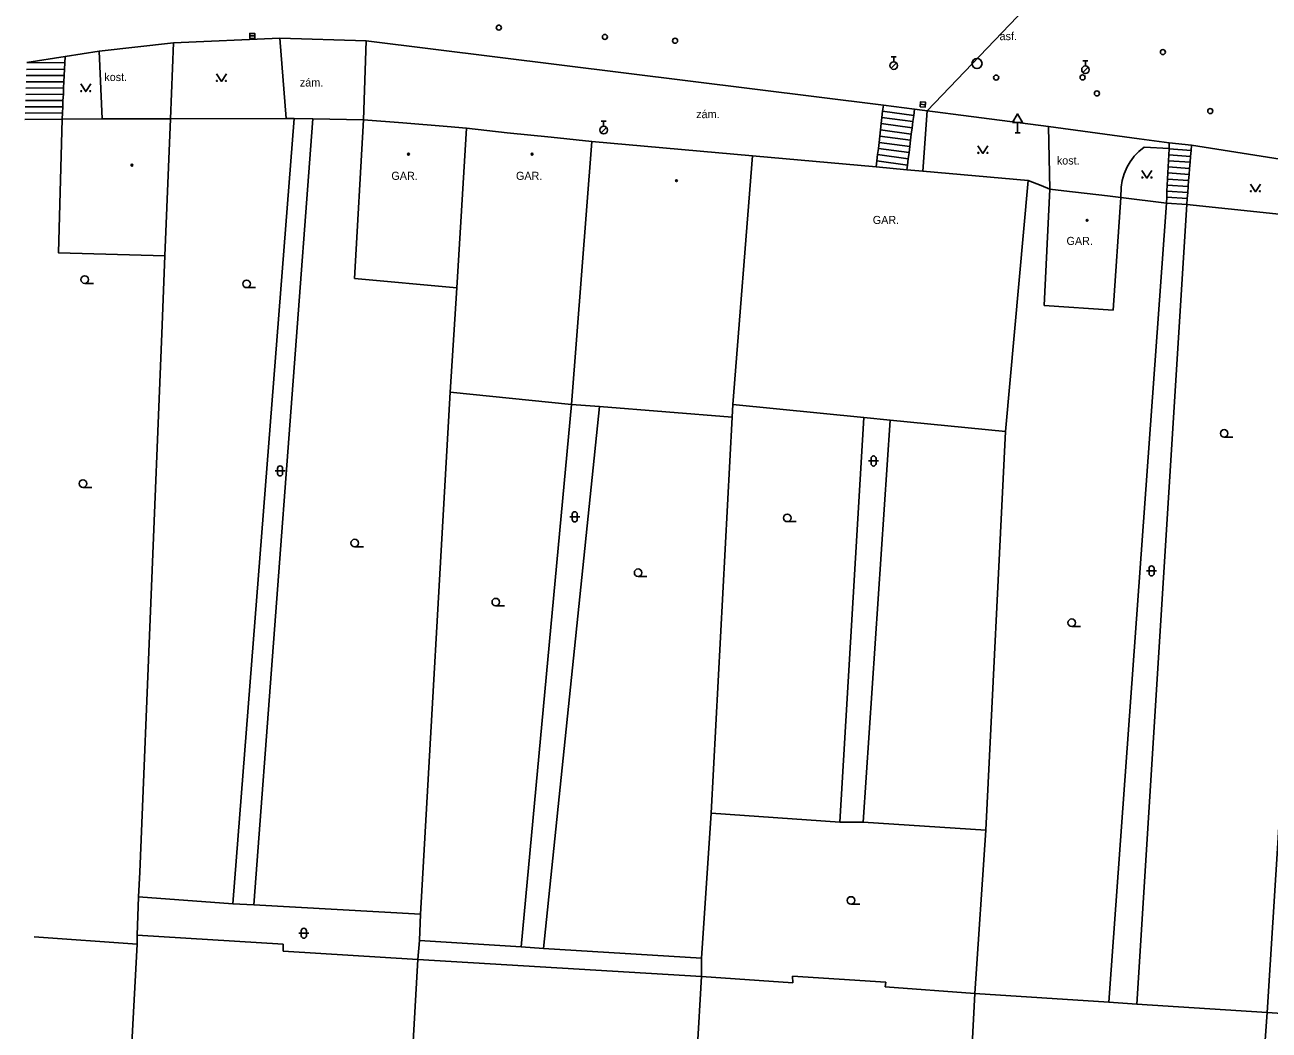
# Model space of a CAD drawing. Extents: x -599770 to -598493, y -1162076 to -1159209.
# Drawn here: x -599538.4 to -599476.7, y -1161787.4 to -1161737.6 of the extents above; entities that cross this region are included whole.
import ezdxf

# ---------------------------------------------------------------- set-up
doc = ezdxf.new("R2010")
doc.units = 0
doc.layers.add('Podklad', color=7, linetype='Continuous')

msp = doc.modelspace()

# ---------------------------------------------------------------- linework, layer by layer
at = {"layer": 'Podklad'}
for p, q in [((-599527.265, -1161738.12), (-599527.015, -1161738.12)), ((-599495.449, -1161739.726), (-599495.184, -1161739.461)), ((-599495.445, -1161739.152), (-599495.195, -1161739.152)), ((-599495.32, -1161739.402), (-599495.32, -1161739.152)), ((-599485.935, -1161739.363), (-599485.685, -1161739.363)), ((-599485.81, -1161739.613), (-599485.81, -1161739.363)), ((-599485.939, -1161739.936), (-599485.674, -1161739.671)), ((-599494.004, -1161741.508), (-599493.756, -1161741.532)), ((-599509.835, -1161742.352), (-599509.585, -1161742.352)), ((-599509.71, -1161742.602), (-599509.71, -1161742.352)), ((-599489.18, -1161742.421), (-599489.18, -1161742.93)), ((-599509.839, -1161742.926), (-599509.574, -1161742.661)), ((-599489.305, -1161742.93), (-599489.055, -1161742.93)), ((-599535.45, -1161750.398), (-599535.012, -1161750.398)), ((-599527.42, -1161750.608), (-599526.983, -1161750.608)), ((-599478.93, -1161758.027), (-599478.492, -1161758.027)), ((-599496.573, -1161759.208), (-599496.073, -1161759.208)), ((-599496.448, -1161759.083), (-599496.448, -1161759.333)), ((-599496.198, -1161759.083), (-599496.198, -1161759.333)), ((-599526.013, -1161759.698), (-599525.513, -1161759.698)), ((-599525.888, -1161759.573), (-599525.888, -1161759.823)), ((-599525.638, -1161759.573), (-599525.638, -1161759.823)), ((-599535.54, -1161760.517), (-599535.102, -1161760.517)), ((-599511.393, -1161761.978), (-599510.893, -1161761.978)), ((-599511.268, -1161761.853), (-599511.268, -1161762.103)), ((-599511.018, -1161761.853), (-599511.018, -1161762.103)), ((-599500.6, -1161762.218), (-599500.163, -1161762.218)), ((-599522.06, -1161763.468), (-599521.622, -1161763.468)), ((-599482.783, -1161764.658), (-599482.283, -1161764.658)), ((-599482.658, -1161764.533), (-599482.658, -1161764.783)), ((-599482.408, -1161764.533), (-599482.408, -1161764.783)), ((-599508, -1161764.938), (-599507.562, -1161764.938)), ((-599515.06, -1161766.398), (-599514.622, -1161766.398)), ((-599486.49, -1161767.418), (-599486.052, -1161767.418)), ((-599497.44, -1161781.198), (-599497.003, -1161781.198)), ((-599524.833, -1161782.638), (-599524.333, -1161782.638)), ((-599524.708, -1161782.513), (-599524.708, -1161782.763)), ((-599524.458, -1161782.513), (-599524.458, -1161782.763))]:
    msp.add_line(p, q, dxfattribs=at)
for points in [[(-599493.87, -1161744.83), (-599493.663, -1161741.84), (-599482.137, -1161729.776)], [(-599525.77, -1161738.23), (-599531.05, -1161738.47)], [(-599521.49, -1161738.36), (-599525.77, -1161738.23)], [(-599525.77, -1161738.23), (-599525.46, -1161742.21)], [(-599536.42, -1161739.14), (-599534.74, -1161738.87)], [(-599531.05, -1161738.47), (-599534.74, -1161738.87)], [(-599534.74, -1161738.87), (-599534.59, -1161742.23)], [(-599531.05, -1161738.47), (-599531.2, -1161742.23)], [(-599521.49, -1161738.36), (-599521.62, -1161742.28)], [(-599495.83, -1161741.55), (-599521.49, -1161738.36)], [(-599538.32, -1161739.44), (-599536.42, -1161739.14)], [(-599536.44, -1161739.46), (-599538.32, -1161739.44)], [(-599536.44, -1161739.46), (-599536.45, -1161739.77)], [(-599536.42, -1161739.14), (-599536.44, -1161739.46)], [(-599536.47, -1161740.08), (-599538.35, -1161740.09)], [(-599536.45, -1161739.77), (-599538.34, -1161739.78)], [(-599536.47, -1161740.08), (-599536.48, -1161740.39)], [(-599536.45, -1161739.77), (-599536.47, -1161740.08)], [(-599528.92, -1161740.005), (-599528.67, -1161740.38), (-599528.42, -1161740.005)], [(-599536.5, -1161740.7), (-599538.37, -1161740.71)], [(-599536.48, -1161740.39), (-599538.36, -1161740.4)], [(-599536.5, -1161740.7), (-599536.51, -1161741.01)], [(-599536.48, -1161740.39), (-599536.5, -1161740.7)], [(-599535.65, -1161740.505), (-599535.4, -1161740.88), (-599535.15, -1161740.505)], [(-599536.53, -1161741.32), (-599538.39, -1161741.33)], [(-599536.51, -1161741.01), (-599538.38, -1161741.02)], [(-599536.53, -1161741.32), (-599536.54, -1161741.63)], [(-599536.51, -1161741.01), (-599536.53, -1161741.32)], [(-599536.55, -1161741.94), (-599538.41, -1161741.95)], [(-599536.54, -1161741.63), (-599538.4, -1161741.64)], [(-599536.55, -1161741.94), (-599536.57, -1161742.25)], [(-599536.54, -1161741.63), (-599536.55, -1161741.94)], [(-599495.87, -1161741.86), (-599495.91, -1161742.17)], [(-599495.83, -1161741.55), (-599495.87, -1161741.86)], [(-599494.33, -1161742.07), (-599495.87, -1161741.86)], [(-599494.29, -1161741.76), (-599495.83, -1161741.55)], [(-599494.29, -1161741.76), (-599494.33, -1161742.07)], [(-599487.64, -1161742.61), (-599494.29, -1161741.76)], [(-599536.57, -1161742.25), (-599538.42, -1161742.26)], [(-599536.57, -1161742.25), (-599536.76, -1161748.88), (-599531.48, -1161749.03)], [(-599536.57, -1161742.25), (-599534.59, -1161742.23), (-599531.2, -1161742.23)], [(-599531.2, -1161742.23), (-599531.48, -1161749.03)], [(-599531.2, -1161742.23), (-599525.46, -1161742.21)], [(-599528.1, -1161781.17), (-599525.06, -1161742.22)], [(-599524.13, -1161742.24), (-599527.07, -1161781.22)], [(-599525.06, -1161742.22), (-599525.46, -1161742.21)], [(-599521.62, -1161742.28), (-599524.13, -1161742.24), (-599525.06, -1161742.22)], [(-599521.62, -1161742.28), (-599522.07, -1161750.16)], [(-599519.67, -1161742.44), (-599521.62, -1161742.28)], [(-599517.48, -1161742.62), (-599519.67, -1161742.44)], [(-599495.94, -1161742.47), (-599495.98, -1161742.78)], [(-599495.91, -1161742.17), (-599495.94, -1161742.47)], [(-599494.41, -1161742.68), (-599495.94, -1161742.47)], [(-599494.37, -1161742.37), (-599495.91, -1161742.17)], [(-599494.37, -1161742.37), (-599494.41, -1161742.68)], [(-599494.33, -1161742.07), (-599494.37, -1161742.37)], [(-599516.52, -1161742.7), (-599517.48, -1161742.62)], [(-599517, -1161750.61), (-599516.52, -1161742.7)], [(-599516.52, -1161742.7), (-599514.5, -1161742.92)], [(-599514.5, -1161742.92), (-599512.31, -1161743.15)], [(-599512.31, -1161743.15), (-599510.3, -1161743.36)], [(-599496.01, -1161743.09), (-599496.05, -1161743.4)], [(-599495.98, -1161742.78), (-599496.01, -1161743.09)], [(-599494.49, -1161743.3), (-599496.01, -1161743.09)], [(-599494.45, -1161742.99), (-599495.98, -1161742.78)], [(-599494.45, -1161742.99), (-599494.49, -1161743.3)], [(-599494.41, -1161742.68), (-599494.45, -1161742.99)], [(-599483.14, -1161743.22), (-599487.64, -1161742.61)], [(-599487.64, -1161742.61), (-599487.57, -1161745.72)], [(-599511.31, -1161756.4), (-599510.3, -1161743.36)], [(-599510.3, -1161743.36), (-599502.33, -1161744.07)], [(-599496.08, -1161743.7), (-599496.12, -1161744.01)], [(-599496.05, -1161743.4), (-599496.08, -1161743.7)], [(-599494.56, -1161743.91), (-599496.08, -1161743.7)], [(-599494.52, -1161743.6), (-599496.05, -1161743.4)], [(-599494.52, -1161743.6), (-599494.56, -1161743.91)], [(-599494.49, -1161743.3), (-599494.52, -1161743.6)], [(-599491.15, -1161743.575), (-599490.9, -1161743.95), (-599490.65, -1161743.575)], [(-599484.06, -1161746.13), (-599484.036, -1161745.631), (-599483.988, -1161745.296), (-599483.898, -1161744.969), (-599483.743, -1161744.614), (-599483.598, -1161744.362), (-599483.432, -1161744.143), (-599483.393, -1161744.092), (-599483.156, -1161743.85), (-599482.89, -1161743.64), (-599481.66, -1161743.7)], [(-599481.65, -1161743.43), (-599483.14, -1161743.22)], [(-599481.66, -1161743.72), (-599481.68, -1161744.02)], [(-599481.65, -1161743.43), (-599481.66, -1161743.7), (-599481.66, -1161743.72)], [(-599480.57, -1161743.8), (-599481.66, -1161743.72)], [(-599480.55, -1161743.54), (-599481.65, -1161743.43)], [(-599480.57, -1161743.8), (-599480.6, -1161744.1)], [(-599480.55, -1161743.54), (-599480.57, -1161743.8)], [(-599474.58, -1161744.48), (-599480.55, -1161743.54)], [(-599502.33, -1161744.07), (-599496.19, -1161744.62), (-599494.67, -1161744.76), (-599493.87, -1161744.83), (-599488.65, -1161745.29), (-599489.78, -1161757.75), (-599495.5, -1161757.18), (-599496.81, -1161757.05), (-599503.3, -1161756.41)], [(-599503.3, -1161756.41), (-599502.33, -1161744.07)], [(-599496.16, -1161744.32), (-599496.19, -1161744.62)], [(-599496.12, -1161744.01), (-599496.16, -1161744.32)], [(-599494.64, -1161744.53), (-599496.16, -1161744.32)], [(-599494.6, -1161744.22), (-599496.12, -1161744.01)], [(-599494.6, -1161744.22), (-599494.64, -1161744.53)], [(-599494.56, -1161743.91), (-599494.6, -1161744.22)], [(-599481.69, -1161744.32), (-599481.71, -1161744.62)], [(-599481.68, -1161744.02), (-599481.69, -1161744.32)], [(-599480.62, -1161744.39), (-599481.69, -1161744.32)], [(-599480.6, -1161744.1), (-599481.68, -1161744.02)], [(-599480.62, -1161744.39), (-599480.65, -1161744.69)], [(-599480.6, -1161744.1), (-599480.62, -1161744.39)], [(-599494.64, -1161744.53), (-599494.67, -1161744.76)], [(-599483.01, -1161744.795), (-599482.76, -1161745.17), (-599482.51, -1161744.795)], [(-599481.72, -1161744.92), (-599481.74, -1161745.22)], [(-599481.71, -1161744.62), (-599481.72, -1161744.92)], [(-599480.67, -1161744.99), (-599481.72, -1161744.92)], [(-599480.65, -1161744.69), (-599481.71, -1161744.62)], [(-599480.67, -1161744.99), (-599480.7, -1161745.29)], [(-599480.65, -1161744.69), (-599480.67, -1161744.99)], [(-599488.65, -1161745.29), (-599488, -1161745.54), (-599487.57, -1161745.72)], [(-599481.75, -1161745.52), (-599481.77, -1161745.82)], [(-599481.74, -1161745.22), (-599481.75, -1161745.52)], [(-599480.72, -1161745.59), (-599481.75, -1161745.52)], [(-599480.7, -1161745.29), (-599481.74, -1161745.22)], [(-599480.72, -1161745.59), (-599480.74, -1161745.89)], [(-599480.7, -1161745.29), (-599480.72, -1161745.59)], [(-599477.63, -1161745.475), (-599477.38, -1161745.85), (-599477.13, -1161745.475)], [(-599487.86, -1161751.49), (-599487.57, -1161745.72)], [(-599487.57, -1161745.72), (-599486.89, -1161745.8)], [(-599486.89, -1161745.8), (-599484.71, -1161746.05)], [(-599484.71, -1161746.05), (-599484.06, -1161746.13)], [(-599484.06, -1161746.13), (-599484.44, -1161751.72)], [(-599484.06, -1161746.13), (-599481.79, -1161746.42)], [(-599481.78, -1161746.12), (-599481.79, -1161746.42)], [(-599481.77, -1161745.82), (-599481.78, -1161746.12)], [(-599480.76, -1161746.19), (-599481.78, -1161746.12)], [(-599480.74, -1161745.89), (-599481.77, -1161745.82)], [(-599480.76, -1161746.19), (-599480.78, -1161746.49)], [(-599480.74, -1161745.89), (-599480.76, -1161746.19)], [(-599481.79, -1161746.42), (-599484.65, -1161786.06)], [(-599483.27, -1161786.15), (-599480.78, -1161746.49)], [(-599480.78, -1161746.49), (-599481.79, -1161746.42)], [(-599480.78, -1161746.49), (-599474.32, -1161747.16), (-599474.5, -1161750.06), (-599476.8, -1161786.57)], [(-599531.48, -1161749.03), (-599531.63, -1161752.89)], [(-599522.07, -1161750.16), (-599517, -1161750.61)], [(-599517.32, -1161755.8), (-599517, -1161750.61)], [(-599484.44, -1161751.72), (-599487.86, -1161751.49)], [(-599531.63, -1161752.89), (-599532.71, -1161779.61)], [(-599517.32, -1161755.8), (-599518.8, -1161781.69)], [(-599517.32, -1161755.8), (-599511.31, -1161756.4)], [(-599511.31, -1161756.4), (-599513.81, -1161783.31)], [(-599512.69, -1161783.4), (-599509.91, -1161756.51)], [(-599511.31, -1161756.4), (-599509.91, -1161756.51), (-599503.33, -1161757.03)], [(-599503.3, -1161756.41), (-599503.33, -1161757.03), (-599504.38, -1161776.68)], [(-599497.99, -1161777.12), (-599496.81, -1161757.05)], [(-599495.5, -1161757.18), (-599496.84, -1161777.12)], [(-599489.78, -1161757.75), (-599490.76, -1161777.53)], [(-599504.38, -1161776.68), (-599504.85, -1161783.88)], [(-599504.38, -1161776.68), (-599497.99, -1161777.12)], [(-599497.99, -1161777.12), (-599496.84, -1161777.12)], [(-599496.84, -1161777.12), (-599490.76, -1161777.53)], [(-599490.76, -1161777.53), (-599491.29, -1161785.62)], [(-599532.71, -1161779.61), (-599532.78, -1161780.83)], [(-599532.78, -1161780.83), (-599532.85, -1161782.74)], [(-599532.78, -1161780.83), (-599528.1, -1161781.17)], [(-599528.1, -1161781.17), (-599527.07, -1161781.22)], [(-599527.07, -1161781.22), (-599518.8, -1161781.69)], [(-599518.8, -1161781.69), (-599518.85, -1161783)], [(-599537.96, -1161782.82), (-599532.85, -1161783.18)], [(-599532.85, -1161783.18), (-599533.41, -1161793.62)], [(-599532.85, -1161782.74), (-599525.6, -1161783.18)], [(-599532.85, -1161783.18), (-599532.85, -1161782.74)], [(-599525.6, -1161783.18), (-599525.61, -1161783.53)], [(-599518.85, -1161783), (-599518.92, -1161783.94)], [(-599513.81, -1161783.31), (-599518.85, -1161783)], [(-599512.69, -1161783.4), (-599513.81, -1161783.31)], [(-599525.61, -1161783.53), (-599518.92, -1161783.94)], [(-599519.53, -1161794.4), (-599518.92, -1161783.94)], [(-599518.92, -1161783.94), (-599504.86, -1161784.78)], [(-599504.85, -1161783.88), (-599512.69, -1161783.4)], [(-599504.85, -1161783.88), (-599504.86, -1161784.78)], [(-599505.5, -1161795.9), (-599504.86, -1161784.78)], [(-599504.86, -1161784.78), (-599500.33, -1161785.09)], [(-599500.33, -1161785.09), (-599500.35, -1161784.77)], [(-599500.35, -1161784.77), (-599495.71, -1161785.06)], [(-599495.71, -1161785.06), (-599495.75, -1161785.3)], [(-599495.75, -1161785.3), (-599491.29, -1161785.62)], [(-599491.29, -1161785.62), (-599491.92, -1161797.71)], [(-599491.29, -1161785.62), (-599484.65, -1161786.06)], [(-599484.65, -1161786.06), (-599483.27, -1161786.15)], [(-599483.27, -1161786.15), (-599476.8, -1161786.57)], [(-599477.58, -1161797.39), (-599476.8, -1161786.57)], [(-599476.8, -1161786.57), (-599472.78, -1161786.84)]]:
    msp.add_lwpolyline(points, dxfattribs=at)
for points in [[(-599527.265, -1161738.245), (-599527.015, -1161738.245), (-599527.015, -1161737.995), (-599527.265, -1161737.995)], [(-599494.016, -1161741.633), (-599493.767, -1161741.656), (-599493.744, -1161741.407), (-599493.993, -1161741.384)], [(-599489.43, -1161742.421), (-599488.93, -1161742.421), (-599489.18, -1161741.988)]]:
    msp.add_lwpolyline(points, close=True, dxfattribs=at)
for centre, radius in [((-599514.91, -1161737.71), 0.125), ((-599509.65, -1161738.17), 0.125), ((-599506.17, -1161738.36), 0.125), ((-599481.97, -1161738.92), 0.125), ((-599495.32, -1161739.59), 0.188), ((-599491.19, -1161739.49), 0.25), ((-599490.24, -1161740.19), 0.125), ((-599485.95, -1161740.18), 0.125), ((-599485.81, -1161739.8), 0.188), ((-599528.895, -1161740.355), 0.025), ((-599528.445, -1161740.355), 0.025), ((-599535.625, -1161740.855), 0.025), ((-599535.175, -1161740.855), 0.025), ((-599485.24, -1161740.97), 0.125), ((-599479.62, -1161741.85), 0.125), ((-599509.71, -1161742.79), 0.188), ((-599519.39, -1161743.99), 0.045), ((-599519.39, -1161743.99), 0.0199), ((-599513.26, -1161743.99), 0.045), ((-599513.26, -1161743.99), 0.0199), ((-599491.125, -1161743.925), 0.025), ((-599490.675, -1161743.925), 0.025), ((-599533.11, -1161744.53), 0.045), ((-599533.11, -1161744.53), 0.0199), ((-599506.1, -1161745.3), 0.045), ((-599506.1, -1161745.3), 0.0199), ((-599482.985, -1161745.145), 0.025), ((-599482.535, -1161745.145), 0.025), ((-599477.605, -1161745.825), 0.025), ((-599477.155, -1161745.825), 0.025), ((-599485.73, -1161747.27), 0.045), ((-599485.73, -1161747.27), 0.0199), ((-599535.45, -1161750.21), 0.188), ((-599527.42, -1161750.42), 0.188), ((-599478.93, -1161757.84), 0.188), ((-599535.54, -1161760.33), 0.188), ((-599500.6, -1161762.03), 0.188), ((-599522.06, -1161763.28), 0.188), ((-599508, -1161764.75), 0.188), ((-599515.06, -1161766.21), 0.188), ((-599486.49, -1161767.23), 0.188), ((-599497.44, -1161781.01), 0.188)]:
    msp.add_circle(centre, radius, dxfattribs=at)
for centre, start, end in [((-599496.323, -1161759.083), 0, 180), ((-599525.763, -1161759.573), 0, 180), ((-599525.763, -1161759.823), 180, 0), ((-599496.323, -1161759.333), 180, 0), ((-599511.143, -1161761.853), 0, 180), ((-599511.143, -1161762.103), 180, 0), ((-599482.533, -1161764.533), 0, 180), ((-599482.533, -1161764.783), 180, 0), ((-599524.583, -1161782.513), 0, 180), ((-599524.583, -1161782.763), 180, 0)]:
    msp.add_arc(centre, 0.125, start, end, dxfattribs=at)

# ---------------------------------------------------------------- texts
for s, p in [('asf.', (-599490.07, -1161738.33)), ('kost.', (-599534.48, -1161740.36)), ('zám.', (-599524.78, -1161740.63)), ('zám.', (-599505.12, -1161742.2)), ('kost.', (-599487.23, -1161744.5)), ('GAR.', (-599520.24, -1161745.26)), ('GAR.', (-599514.06, -1161745.26)), ('GAR.', (-599496.36, -1161747.45)), ('GAR.', (-599486.75, -1161748.49))]:
    msp.add_text(s, height=0.4, dxfattribs=at).set_placement(p)

doc.saveas('drawing.dxf')
